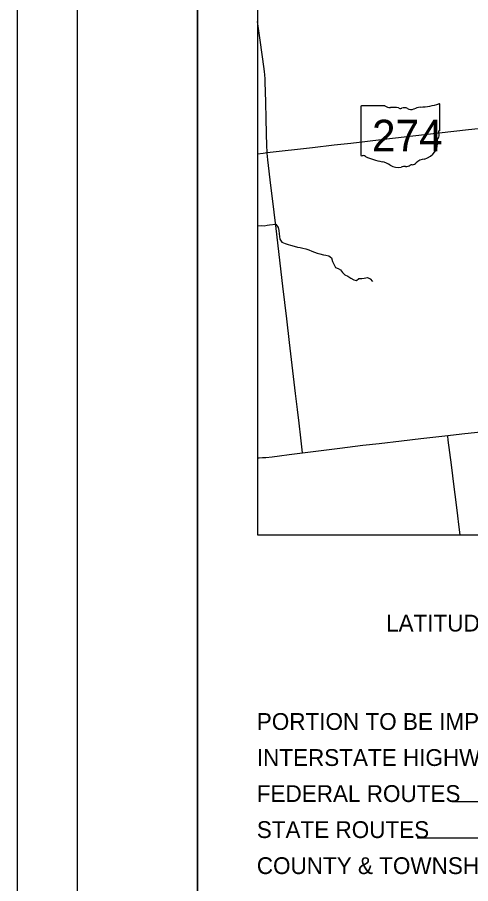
# Model space of a CAD drawing. Extents: x -5.9 to 34, y 0 to 22.
# Drawn here: x 0 to 3.78, y 11.1 to 18.31 of the extents above; entities that cross this region are included whole.
import ezdxf

# ---------------------------------------------------------------- set-up
doc = ezdxf.new("R2010")
doc.units = 0
for name, color, linetype in [('GM_X_County_Road', 7, 'Continuous'), ('GM_X_Minor_River', 7, 'Continuous'), ('GM_X_State_Route', 7, 'Continuous'), ('GM_X_State_Shield', 7, 'Continuous'), ('GM_X_Township_Road', 7, 'Continuous'), ('SH_Border', 7, 'Continuous'), ('SH_Cut_Line', 7, 'Continuous'), ('SH_Data', 7, 'Continuous'), ('SH_Text', 7, 'Continuous')]:
    doc.layers.add(name, color=color, linetype=linetype)

msp = doc.modelspace()

# ---------------------------------------------------------------- linework, layer by layer
at = {"layer": 'GM_X_County_Road'}
msp.add_lwpolyline([(2, 14.6431), (2.0142, 14.6428), (2.0416, 14.6435), (2.0702, 14.6456), (2.1221, 14.6514), (2.1826, 14.659), (2.2652, 14.6692), (2.3757, 14.6832), (2.6864, 14.7228), (2.8764, 14.746), (3.0134, 14.7622), (3.1985, 14.7845), (3.3604, 14.8023), (3.5604, 14.8247), (3.5842, 14.8273), (3.7025, 14.8404), (3.8842, 14.8597)], dxfattribs=at)
at = {"layer": 'GM_X_Minor_River'}
for points in [[(2, 16.57), (2.0059, 16.5726), (2.0325, 16.576), (2.0559, 16.574), (2.081, 16.5782), (2.0999, 16.5816), (2.153, 16.5868), (2.173, 16.5599)], [(2.173, 16.5599), (2.1779, 16.5355), (2.182, 16.5058), (2.1839, 16.4853), (2.1873, 16.4617), (2.2036, 16.4364), (2.2306, 16.4253), (2.2547, 16.418), (2.2751, 16.4124), (2.3052, 16.4027), (2.3346, 16.3962), (2.3565, 16.392), (2.3768, 16.3879), (2.4025, 16.3829), (2.4273, 16.3726), (2.4529, 16.363), (2.474, 16.3551), (2.498, 16.3448), (2.5184, 16.3399), (2.5485, 16.3325), (2.5689, 16.3284), (2.5946, 16.3242), (2.6155, 16.3079), (2.6256, 16.2758), (2.635, 16.2529), (2.649, 16.2261), (2.6731, 16.2173), (2.6926, 16.2079), (2.7081, 16.1841), (2.7282, 16.1655), (2.7515, 16.1529), (2.7762, 16.1389), (2.8017, 16.1232), (2.8243, 16.1183), (2.845, 16.1354), (2.87, 16.1357), (2.889, 16.1385), (2.9155, 16.1426), (2.9388, 16.1323), (2.9589, 16.1084)]]:
    msp.add_lwpolyline(points, dxfattribs=at)
at = {"layer": 'GM_X_State_Route'}
msp.add_lwpolyline([(2, 17.1729), (2.0463, 17.1785), (2.0801, 17.1824), (2.4575, 17.226), (2.6377, 17.2469), (2.7761, 17.2622), (2.8934, 17.276), (3.0526, 17.2945), (3.3923, 17.3327), (3.7566, 17.3738), (3.9962, 17.401)], dxfattribs=at)
at = {"layer": 'GM_X_State_Shield'}
for p, q in [((2.8606, 17.5644), (2.8606, 17.1642)), ((3.0602, 17.5713), (2.8671, 17.5713)), ((3.5198, 17.3719), (3.5198, 17.5812)), ((3.5197, 17.3719), (3.5198, 17.3719))]:
    msp.add_line(p, q, dxfattribs=at)
for centre, major_axis, start_param, end_param in [((2.8682, 17.5653), (0.00764, 0), 1.712693, 3.28349), ((3.1061, 17.6178), (0.0741, 0), 4.042523, 4.731795), ((3.1307, 17.3466), (0.2659, 0), 1.404758, 1.657858), ((3.1911, 17.5674), (0.0214, 0), 3.836095, 5.185415), ((3.2224, 17.5211), (0.0444, 0), 0.950623, 2.079405), ((3.2798, 17.5846), (0.0534, 0), 4.081561, 5.145723), ((3.3742, 17.4491), (0.1406, 0), 1.699011, 2.107814), ((3.285, 18.117), (0.699, 0), 4.814394, 5.042369), ((3.5125, 17.5821), (0.00734, 0), 6.141152, 7.989035), ((3.5461, 17.2843), (0.0496, 0), 2.387724, 3.262537), ((3.5181, 17.3565), (0.0114, 0), 1.883978, 3.671073), ((3.4459, 17.33), (0.0682, 0), 5.934695, 6.695948), ((3.512, 17.3711), (0.00785, 0), 5.05454, 6.418171), ((3.3242, 17.2576), (0.1748, 0), 5.101752, 6.440018), ((2.8683, 17.1633), (0.0077, 0), 3.00124, 4.508301), ((2.8694, 17.2043), (0.0588, 0), 4.665946, 4.897461), ((2.8815, 17.1411), (0.0212, 0), 0.519207, 1.627899), ((3.1491, 17.5007), (0.5048, 0), 4.195997, 4.488961), ((2.9986, 16.9844), (0.1579, 0), 0.823519, 1.323587), ((3.2766, 17.1254), (0.0565, 0), 4.937069, 5.64225), ((3.3979, 17.0518), (0.0958, 0), 1.647645, 2.488434), ((3.1694, 17.1391), (0.1002, 0), 4.026481, 4.996735), ((3.2273, 17.0007), (0.0824, 0), 1.495662, 1.94098), ((3.2347, 17.1091), (0.0534, 0), 4.691044, 5.507374), ((3.283, 17.0704), (0.015, 0), 1.147584, 2.315152)]:
    msp.add_ellipse(centre, major_axis=major_axis, ratio=0.8, start_param=start_param, end_param=end_param, dxfattribs=at)
at = {"layer": 'GM_X_Township_Road'}
for points in [[(2.0864, 17.1233), (2.0802, 17.1792), (2.0801, 17.1824), (2.0798, 17.1952), (2.0786, 17.2325), (2.0727, 17.4623), (2.0695, 17.6052), (2.0648, 17.768), (2.0638, 17.7938), (2.0616, 17.8339), (2.0598, 17.8543), (2.0567, 17.8797), (2.0226, 18.1197), (2, 18.2752)], [(2.3757, 14.6832), (2.3597, 14.8082), (2.3463, 14.9305), (2.3333, 15.0429), (2.3173, 15.1786), (2.2671, 15.6007), (2.2435, 15.7982), (2.2117, 16.071), (2.1554, 16.5512), (2.14, 16.6858), (2.1289, 16.7783), (2.1123, 16.9078), (2.0866, 17.1213), (2.0864, 17.1233)], [(3.6881, 14), (3.6775, 14.087), (3.6684, 14.1584), (3.6534, 14.2717), (3.6372, 14.3998), (3.6145, 14.5836), (3.5892, 14.7883), (3.5848, 14.8223), (3.5842, 14.8273)]]:
    msp.add_lwpolyline(points, dxfattribs=at)
at = {"layer": 'SH_Border'}
for points in [[(0.5, 21.5), (1.5, 21.5), (1.5, 0.5), (0.5, 0.5)], [(1.5, 21.5), (33.5, 21.5), (33.5, 0.5), (1.5, 0.5)]]:
    msp.add_lwpolyline(points, close=True, dxfattribs=at)
at = {"layer": 'SH_Cut_Line'}
msp.add_lwpolyline([(0, 0), (34, 0), (34, 22), (0, 22)], close=True, dxfattribs=at)
at = {"layer": 'SH_Data'}
for p, q in [((2, 21), (2, 14)), ((2, 14), (9, 14)), ((7.7, 11.7767), (3.6192, 11.7767)), ((7.7, 11.4767), (3.3288, 11.4767))]:
    msp.add_line(p, q, dxfattribs=at)

# ---------------------------------------------------------------- texts
at = {"layer": 'GM_X_State_Shield'}
msp.add_text('274', height=0.26367, dxfattribs=at).set_placement((2.9537, 17.1924))
at = {"layer": 'SH_Text'}
for s, p in [('LATITUDE:  40°26\'45"  N   LONGITUDE:  83°49\'10" W', (3.071, 13.1959)), ('PORTION TO BE IMPROVED', (1.9944, 12.3767)), ('INTERSTATE HIGHWAY', (1.9944, 12.0767)), ('FEDERAL ROUTES', (1.9944, 11.7767)), ('STATE ROUTES', (1.9944, 11.4767)), ('COUNTY & TOWNSHIP ROADS', (1.9944, 11.1767))]:
    msp.add_text(s, height=0.14, dxfattribs=at).set_placement(p)

doc.saveas('drawing.dxf')
